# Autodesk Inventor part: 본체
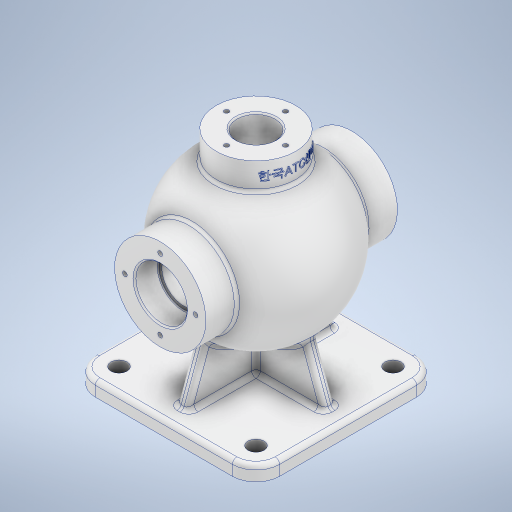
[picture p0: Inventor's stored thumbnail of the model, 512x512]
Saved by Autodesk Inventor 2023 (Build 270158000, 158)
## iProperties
Created: 2023-07
Part Number: 본체
Material: 알루미늄 6061
Document SubType Name: Modeling
Designer: Owner
Density: 2.7 g/cm^3
Appearance: 알루미늄 - 평지
Mass: 1526.72 g
Surface Area: 1173.82 cm^2
Volume: 565.453 cm^3
Author: Owner
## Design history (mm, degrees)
sketch "스케치2"
  geometry: L1 (62.5, -62.5)-(-62.5, -62.5); L2 (-62.5, -62.5)-(-62.5, 62.5); L3 (-62.5, 62.5)-(62.5, 62.5); L4 (62.5, 62.5)-(62.5, -62.5); L5 (62.5, -62.5)-(-62.5, 62.5); L6 (-62.5, -62.5)-(62.5, 62.5); 1 further point
  constraints: 12 end point, 2 midpoint, 2 parallel, 1 horizontal, 1 perpendicular
  dimensions: "d0" = 125 distance of L1.start L1.end; "d1" = 125 distance of L1.end L2.end
extrude "돌출1" new body sketch "스케치2" distance "d2" = 10; taper "d3" = 0 deg
fillet "모깎기1" dims "d5" = 16
sketch "스케치4"
  geometry: C1 r 5.5 at (-46.5, 46.5); C2 r 5.5 at (46.5, 46.5); C3 r 5.5 at (46.5, -46.5); C4 r 5.5 at (-46.5, -46.5); A1 r 16 centre (-46.5, 46.5) between (-46.5, 62.5) and (-62.5, 46.5) reference; A2 r 16 centre (-46.5, -46.5) between (-62.5, -46.5) and (-46.5, -62.5) reference; A3 r 16 centre (46.5, -46.5) between (46.5, -62.5) and (62.5, -46.5) reference; A4 r 16 centre (46.5, 46.5) between (62.5, 46.5) and (46.5, 62.5) reference; 1 further point
  constraints: 4 centre point, 4 coincident
  dimensions: "d6" = 11 diameter of C1; "d7" = 11 diameter of C2; "d8" = 11 diameter of C3; "d9" = 11 diameter of C4
extrude "돌출2" cut sketch "스케치4" extent not by distance; stored distance "d10" = 0; taper "d11" = 0 deg
fillet "모깎기2" dims "d12" = 3
sketch "스케치5"
  geometry: L1 (85, 65)-(85, -65); L2 (85, -65)-(54, -65); L3 (0, 46.5)-(0, -46.5) reference; L4 (85, 65)-(54, 65); L5 (54, 65)-(54, 44.215); L6 (54, -65)-(54, -44.215); A1 r 54 centre (85, 0) between (54, 44.215) and (54, -44.215); 3 further points
  constraints: 10 end point, 2 midpoint, 2 perpendicular, 2 point on circle, 2 vertical, 1 centre point, 1 coincident, 1 collinear, 1 horizontal, 1 horizontal alignment
  dimensions: "d13" = 130 distance of L1.start L1.end; "d14" = 85 distance from line of L3 point (85, 0); "d15" = 31 distance of L1.end L2.end; "d16" = 54 radius of A1
revolve "회전1" sketch "스케치5" stored, may be unused: angle "d17" = 90 deg
sketch "스케치6"
  geometry: L1 (7, -62.5)-(0, -62.5) reference; L2 (0, -62.5)-(0, 62.5) reference; L3 (0, 62.5)-(7, 62.5) reference; L4 (10, 59.5)-(10, -59.5) reference; L5 (54, 65)-(116, 65) reference; L6 (116, 65)-(116, 44.215) reference; L7 (116, -44.215)-(116, -65) reference; L8 (116, -65)-(54, -65) reference; L9 (54, -65)-(54, -44.215) reference; L10 (54, 44.215)-(54, 65) reference; L11 (10, 46.5)-(10, -46.5) reference; L12 (10, 50.5)-(83.668, 23.687); L13 (83.668, 23.687)-(83.668, -23.687); L14 (83.668, -23.687)-(10, -50.5); A1 r 3 centre (7, -59.5) between (7, -62.5) and (10, -59.5) reference; A2 r 3 centre (7, 59.5) between (10, 59.5) and (7, 62.5) reference; A3 r 54 centre (85, 0) between (116, -44.215) and (116, 44.215) reference; A4 r 54 centre (85, 0) between (54, 44.215) and (54, -44.215) reference; 7 further points
  constraints: 6 end point, 2 midpoint, 2 point on line, 1 parallel
  dimensions: "d18" = 12 vertical distance of L12.start point (3.5, 62.5); "d19" = 20 deg angle of L12 L3; "d20" = 12 vertical distance of point (3.5, -62.5) L14.end; "d21" = 20 deg angle of L1 L14; "d22" = 83.66811 distance between parallel lines of L2 L13
extrude "돌출3" join sketch "스케치6" stored distance "d23" = 8; taper "d24" = 0 deg
sketch "스케치7"
  geometry: L1 (62.5, 7)-(62.5, 0) reference; L2 (62.5, 0)-(-62.5, 0) reference; L3 (-62.5, 0)-(-62.5, 7) reference; L4 (-59.5, 10)-(-4, 10) reference; L5 (-4, 10)-(-4, 31.148) reference; L6 (4, 31.148)-(4, 10) reference; L7 (4, 10)-(59.5, 10) reference; L8 (-46.5, 10)-(46.5, 10) reference; L9 (50.5, 10)-(41.398, 35.008); A1 r 3 centre (59.5, 7) between (62.5, 7) and (59.5, 10) reference; A2 r 3 centre (-59.5, 7) between (-59.5, 10) and (-62.5, 7) reference; A3 r 54 centre (0, 85) between (4, 31.148) and (-4, 31.148) reference; 2 further points
  constraints: 2 end point, 1 midpoint, 1 point on line
  dimensions: "d25" = 12 horizontal distance of point (62.5, 3.5) L9.start; "d26" = 20 deg angle of L1 L9
feature "리브1" sketch "스케치7" dims "d27" = 1, "d28" = 8, "d29" = 0, "d30" = 0, "d31" = 1, "d32" = 1
sketch "스케치8"
  geometry: C1 r 31 at (0, 0) reference; C2 r 15 at (0, 0); 1 further point
  constraints: 1 centre point, 1 coincident
  dimensions: "d33" = 30 diameter of C2
fillet "모깎기3" dims "d48" = 3
fillet "모깎기4" dims "d49" = 3
node "작업 평면1"
sketch "스케치11"
  geometry: C1 r 27 at (0, 0); 1 further point
  constraints: 1 centre point, 1 coincident
  dimensions: "d51" = 54 diameter of C1
extrude "돌출5" join sketch "스케치11" stored distance "d52" = 10; taper "d53" = 0 deg
sketch "스케치12"
  geometry: C1 r 27 at (0, 0) reference; C2 r 13 at (0, 0)
  constraints: 1 centre point, 1 coincident
  dimensions: "d54" = 26 diameter of C2
sketch "스케치13" dims "d57" = 40
  geometry: C1 r 13 at (0, 0) reference; C2 r 27 at (0, 0) reference; 2 further points
  constraints: 2 vertical alignment, 1 coincident, 2 other
hole "구멍2" sketch "스케치13" at (0, 20) diameter "d58" = 3.242; stored, may be unused: countersink angle "d62" = 90 deg, drill point angle "d64" = 118 deg; dims "d59" = 9, "d60" = 4, "d61" = 2, "d63" = 11
fillet "모깎기5" dims "d68" = 3
fillet "모깎기6" dims "d69" = 3
sketch "스케치14"
  geometry: L1 (0, 0)-(140.594, 0); C1 r 44 at (85, 0); 3 further points
  constraints: 2 end point, 1 centre point, 1 coincident, 1 horizontal, 1 horizontal alignment
  dimensions: "d70" = 88 diameter of C1; "d72" = 85 distance of point (0, 0) C1.centre
revolve "회전2" stored, may be unused: angle "d76" = 90 deg
extrude "돌출7" cut sketch "스케치8" extent not by distance; stored distance "d77" = 0; taper "d78" = 0 deg
extrude "돌출8" cut sketch "스케치12" stored distance "d79" = 10; taper "d80" = 0 deg
sketch "스케치16"
  geometry: C1 r 31 at (0, 0) reference; C2 r 17.5 at (0, 0); 1 further point
  constraints: 1 centre point, 1 coincident
  dimensions: "d91" = 35 diameter of C2
extrude "돌출9" cut sketch "스케치16" distance "d92" = 16; taper "d93" = 0 deg
fillet "모깎기8" dims "d94" = 0.6
fillet "모깎기9" dims "d95" = 0.6
chamfer "모따기2" distance "d96" = 1; stored, may be unused: second distance "d97" = 2, angle "d98" = 45 deg
node "작업 평면2"
sketch "스케치17"
  geometry: L1 (150, -27)-(150, 27) reference; L2 (0, 46.5)-(0, -46.5) reference; 3 further points
  constraints: 1 horizontal alignment, 1 midpoint, 1 other
  dimensions: "d100" = 9 distance from line of L1 point (141, 0)
feature "엠보싱1" sketch "스케치17" dims "d101" = 0.5, "d102" = 0
fillet "모깎기10" dims "d103" = 3
sketch "스케치18" dims "d104" = 48
  geometry: C1 r 31 at (0, 0) reference; C2 r 18.5 at (0, 0) reference; 3 further points
  constraints: 2 vertical alignment, 1 coincident, 2 other
hole "구멍3" sketch "스케치18" at (0, 24) diameter "d105" = 3.242; stored, may be unused: countersink angle "d109" = 90 deg, drill point angle "d111" = 118 deg; dims "d106" = 12, "d107" = 4, "d108" = 2, "d110" = 15
feature "ɕ耀ɗ耀ə耀ɛ耀ɝ耀ɟ耀ɡ耀ɣ耀" dims "d0" = 125, "d1" = 125, "d2" = 10, "d3" = 0, "d5" = 16, "d6" = 11, "d7" = 11, "d8" = 11, "d9" = 11, "d10" = 0, "d11" = 0, "d12" = 3, "d13" = 130, "d14" = 85, "d15" = 31, "d16" = 54, "d17" = 90 deg, "d18" = 12, "d19" = 20 deg, "d20" = 12, "d21" = 20 deg, "d22" = 83.66811, "d23" = 8, "d24" = 0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
node "솔리드1"
mirror "미러1"
pattern_circular "원형 패턴3" dims angle "d74" = 360 deg
mirror "미러3"
pattern_circular "원형 패턴6" dims angle "d113" = 360 deg
mirror "미러5"
node "절단 모서리 투영1"
node "절단 모서리 투영2"
feature "A9D066F2-1C7D-4E18-AEED-F7BC21143FA4" dims "d58" = 3.242, "d59" = 9, "d60" = 4, "d61" = 2, "d62" = 90 deg, "d63" = 11, "d64" = 118 deg
